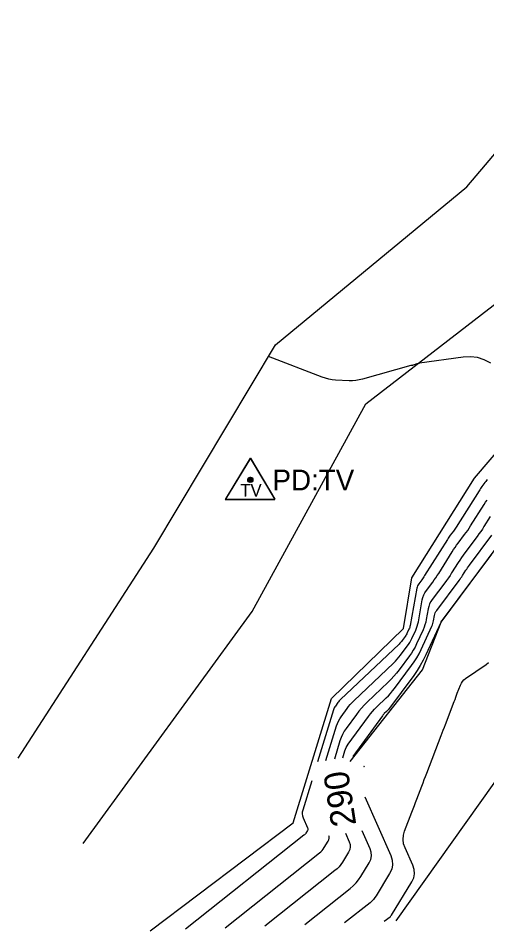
# Model space of a CAD drawing. Extents: x 1574966 to 1597594, y 720505 to 737840.
# Drawn here: x 1577468 to 1577580.8, y 724242.8 to 724462.3 of the extents above; entities that cross this region are included whole.
import ezdxf

# ---------------------------------------------------------------- set-up
doc = ezdxf.new("R2010")
doc.units = 0
for name, color, linetype in [('Default', 7, 'Continuous'), ('R_Contour Annot', 7, 'Continuous'), ('R_Contours', 7, 'Continuous'), ('S_BREAKLINE', 7, 'Continuous'), ('S_GRD_PT_SYM', 7, 'Continuous'), ('S_SECONDARY_CTL', 7, 'Continuous'), ('S_SECONDARY_CTL_ANNOT', 7, 'Continuous'), ('S_STREAM', 7, 'Continuous')]:
    doc.layers.add(name, color=color, linetype=linetype)

msp = doc.modelspace()

# ---------------------------------------------------------------- linework, layer by layer
at = {"layer": 'Default'}
for points in [[(1577523.86, 724351.22), (1577523.86, 724351.27), (1577523.86, 724351.22), (1577523.81, 724351.22), (1577523.86, 724351.22), (1577523.86, 724351.17), (1577523.86, 724351.22), (1577523.91, 724351.22)], [(1577523.86, 724351.22), (1577523.86, 724351.27), (1577523.86, 724351.22), (1577523.81, 724351.22), (1577523.86, 724351.22), (1577523.86, 724351.17), (1577523.86, 724351.22), (1577523.91, 724351.22)], [(1577523.86, 724351.22), (1577523.86, 724351.27), (1577523.86, 724351.22), (1577523.81, 724351.22), (1577523.86, 724351.22), (1577523.86, 724351.17), (1577523.86, 724351.22), (1577523.91, 724351.22)], [(1577523.91, 724351.26), (1577523.91, 724351.31), (1577523.91, 724351.26), (1577523.85, 724351.26), (1577523.91, 724351.26), (1577523.91, 724351.21), (1577523.91, 724351.26), (1577523.96, 724351.26)], [(1577523.91, 724351.26), (1577523.91, 724351.31), (1577523.91, 724351.26), (1577523.85, 724351.26), (1577523.91, 724351.26), (1577523.91, 724351.21), (1577523.91, 724351.26), (1577523.96, 724351.26)], [(1577523.91, 724351.26), (1577523.91, 724351.31), (1577523.91, 724351.26), (1577523.85, 724351.26), (1577523.91, 724351.26), (1577523.91, 724351.21), (1577523.91, 724351.26), (1577523.96, 724351.26)]]:
    msp.add_lwpolyline(points, dxfattribs=at)
at = {"layer": 'R_Contours'}
for points in [[(1577581.81, 724379.31), (1577580.23, 724380.12), (1577578.59, 724380.63), (1577576.89, 724380.83), (1577575.12, 724380.74), (1577564.65, 724379.28), (1577564.48, 724379.26), (1577564.31, 724379.22), (1577564.15, 724379.18), (1577563.98, 724379.12), (1577563.1, 724378.81), (1577563.05, 724378.8), (1577563, 724378.79), (1577562.96, 724378.78), (1577562.91, 724378.78), (1577562.71, 724378.76), (1577562.66, 724378.76), (1577562.61, 724378.75), (1577562.56, 724378.74), (1577562.51, 724378.73), (1577550.89, 724375.46), (1577550.09, 724375.27), (1577549.29, 724375.14), (1577548.48, 724375.08), (1577547.67, 724375.09), (1577544.39, 724375.25), (1577543.58, 724375.32), (1577542.78, 724375.46), (1577541.99, 724375.66), (1577541.22, 724375.92), (1577528.31, 724380.91)], [(1577580.94, 724351.3), (1577580.75, 724351.06), (1577580.56, 724350.82), (1577580.38, 724350.58), (1577579.64, 724349.61), (1577579.46, 724349.36), (1577579.28, 724349.12), (1577579.11, 724348.86), (1577578.95, 724348.61), (1577573.46, 724339.89), (1577573.3, 724339.64), (1577573.13, 724339.38), (1577572.95, 724339.14), (1577572.77, 724338.89), (1577572.04, 724337.92), (1577571.86, 724337.68), (1577571.69, 724337.43), (1577571.52, 724337.18), (1577571.35, 724336.92), (1577565.86, 724328.19), (1577565.69, 724327.94), (1577565.52, 724327.69), (1577565.35, 724327.44), (1577565.17, 724327.2), (1577564.44, 724326.23), (1577564.28, 724325.98), (1577564.14, 724325.72), (1577564.04, 724325.44), (1577563.97, 724325.15), (1577562.37, 724316.22), (1577562.32, 724315.98), (1577562.26, 724315.75), (1577562.18, 724315.52), (1577562.08, 724315.29), (1577561.68, 724314.41), (1577561.57, 724314.19), (1577561.45, 724313.98), (1577561.32, 724313.77), (1577561.18, 724313.57), (1577560.45, 724312.6), (1577560.28, 724312.37), (1577560.1, 724312.16), (1577559.9, 724311.95), (1577559.7, 724311.75), (1577545.64, 724298.42), (1577545.46, 724298.24), (1577545.29, 724298.05), (1577545.12, 724297.86), (1577544.97, 724297.65), (1577544.37, 724296.83), (1577544.23, 724296.62), (1577544.11, 724296.39), (1577544.01, 724296.17), (1577543.92, 724295.93), (1577540.08, 724283.41)], [(1577542.1, 724283.72), (1577544.66, 724292.06), (1577544.87, 724292.64), (1577545.12, 724293.2), (1577545.41, 724293.73), (1577545.75, 724294.24), (1577547.2, 724296.24), (1577547.57, 724296.73), (1577547.97, 724297.2), (1577548.38, 724297.66), (1577548.82, 724298.09), (1577558.39, 724307.17), (1577558.84, 724307.61), (1577559.27, 724308.07), (1577559.68, 724308.55), (1577560.07, 724309.05), (1577561.69, 724311.23), (1577562, 724311.67), (1577562.29, 724312.13), (1577562.55, 724312.6), (1577562.79, 724313.09), (1577563.7, 724315.06), (1577563.91, 724315.56), (1577564.09, 724316.07), (1577564.23, 724316.59), (1577564.35, 724317.12), (1577565.28, 724322.35), (1577565.43, 724322.96), (1577565.64, 724323.54), (1577565.92, 724324.09), (1577566.27, 724324.61), (1577567.8, 724326.64), (1577568.18, 724327.16), (1577568.54, 724327.68), (1577568.9, 724328.2), (1577569.24, 724328.74), (1577572.5, 724333.91), (1577572.84, 724334.45), (1577573.2, 724334.98), (1577573.57, 724335.5), (1577573.95, 724336.01), (1577575.49, 724338.05), (1577575.87, 724338.57), (1577576.23, 724339.09), (1577576.59, 724339.62), (1577576.94, 724340.16), (1577580.17, 724345.29), (1577580.52, 724345.83), (1577580.88, 724346.36)], [(1577581.67, 724342.42), (1577580.14, 724339.99), (1577579.75, 724339.39), (1577579.35, 724338.79), (1577578.94, 724338.21), (1577578.51, 724337.63), (1577575.55, 724333.7), (1577575.12, 724333.12), (1577574.71, 724332.53), (1577574.3, 724331.93), (1577573.91, 724331.32), (1577572.36, 724328.87), (1577571.97, 724328.26), (1577571.57, 724327.66), (1577571.15, 724327.06), (1577570.72, 724326.48), (1577567.71, 724322.48), (1577567.35, 724321.95), (1577567.07, 724321.39), (1577566.85, 724320.8), (1577566.7, 724320.18), (1577566.25, 724317.63), (1577566.12, 724317.01), (1577565.94, 724316.39), (1577565.73, 724315.78), (1577565.48, 724315.19), (1577563.91, 724311.77), (1577563.54, 724311.01), (1577563.13, 724310.28), (1577562.68, 724309.57), (1577562.2, 724308.88), (1577559.69, 724305.51), (1577559.08, 724304.73), (1577558.45, 724303.99), (1577557.78, 724303.27), (1577557.09, 724302.58), (1577552, 724297.76), (1577551.31, 724297.07), (1577550.65, 724296.35), (1577550.02, 724295.61), (1577549.43, 724294.83), (1577546.98, 724291.45), (1577546.51, 724290.75), (1577546.11, 724290.01), (1577545.76, 724289.25), (1577545.48, 724288.45), (1577544.13, 724284.03)], [(1577546.15, 724284.35), (1577546.68, 724286.06), (1577546.82, 724286.47), (1577547, 724286.87), (1577547.21, 724287.26), (1577547.46, 724287.62), (1577552.33, 724294.34), (1577552.8, 724294.95), (1577553.29, 724295.54), (1577553.81, 724296.11), (1577554.36, 724296.65), (1577556.59, 724298.77), (1577557.14, 724299.31), (1577557.66, 724299.87), (1577558.16, 724300.46), (1577558.63, 724301.06), (1577562.71, 724306.54), (1577563.36, 724307.47), (1577563.97, 724308.43), (1577564.52, 724309.42), (1577565.03, 724310.45), (1577567.61, 724316.07), (1577567.74, 724316.38), (1577567.85, 724316.69), (1577567.94, 724317.01), (1577568.01, 724317.33), (1577568.24, 724318.64), (1577568.32, 724318.96), (1577568.43, 724319.26), (1577568.57, 724319.55), (1577568.76, 724319.83), (1577574.18, 724327.03), (1577574.4, 724327.33), (1577574.61, 724327.63), (1577574.81, 724327.93), (1577575.01, 724328.24), (1577575.79, 724329.48), (1577575.99, 724329.79), (1577576.19, 724330.09), (1577576.41, 724330.39), (1577576.62, 724330.68), (1577582.06, 724337.91)], [(1577581.95, 724333.32), (1577577.69, 724327.67), (1577577.69, 724327.66), (1577577.68, 724327.65), (1577577.68, 724327.65), (1577577.67, 724327.64), (1577577.66, 724327.61), (1577577.65, 724327.6), (1577577.65, 724327.6), (1577577.64, 724327.59), (1577577.64, 724327.58), (1577569.81, 724317.17), (1577569.79, 724317.16), (1577569.79, 724317.14), (1577569.78, 724317.12), (1577569.78, 724317.11), (1577569.76, 724317.03), (1577569.76, 724317.01), (1577569.75, 724316.99), (1577569.75, 724316.98), (1577569.74, 724316.96), (1577566.14, 724309.13), (1577565.51, 724307.84), (1577564.81, 724306.58), (1577564.05, 724305.37), (1577563.22, 724304.19), (1577557.12, 724296.01), (1577557.01, 724295.87), (1577556.9, 724295.73), (1577556.78, 724295.61), (1577556.66, 724295.48), (1577556.15, 724295), (1577556.02, 724294.88), (1577555.91, 724294.75), (1577555.8, 724294.62), (1577555.69, 724294.48), (1577548.61, 724284.73)], [(1577556.15, 724245.05), (1577557.54, 724246.15), (1577557.63, 724246.23), (1577557.72, 724246.33), (1577557.8, 724246.42), (1577557.87, 724246.53), (1577562.76, 724254.54), (1577563.22, 724255.51), (1577563.41, 724256.5), (1577563.35, 724257.5), (1577563.02, 724258.52), (1577561.15, 724262.71), (1577560.81, 724263.71), (1577560.68, 724264.72), (1577560.75, 724265.73), (1577561.04, 724266.75), (1577562.79, 724271.31), (1577563.09, 724272.09), (1577563.39, 724272.87), (1577563.69, 724273.65), (1577563.99, 724274.43), (1577565.18, 724277.55), (1577565.48, 724278.34), (1577565.78, 724279.12), (1577566.08, 724279.9), (1577566.38, 724280.68), (1577569.85, 724289.71), (1577570.1, 724290.38), (1577570.36, 724291.05), (1577570.61, 724291.71), (1577570.86, 724292.38), (1577572.99, 724297.95), (1577573.17, 724298.44), (1577573.36, 724298.93), (1577573.55, 724299.41), (1577573.73, 724299.9), (1577574.48, 724301.85), (1577574.7, 724302.31), (1577574.98, 724302.73), (1577575.32, 724303.1), (1577575.72, 724303.42), (1577580.68, 724306.85), (1577581.22, 724307.28)], [(1577538.68, 724278.86), (1577536.52, 724271.82), (1577536.41, 724271.34), (1577536.4, 724270.87), (1577536.47, 724270.41), (1577536.63, 724269.95), (1577537.7, 724267.54), (1577537.76, 724267.37), (1577537.77, 724267.21), (1577537.74, 724267.05), (1577537.66, 724266.89), (1577537.28, 724266.27), (1577537.18, 724266.12), (1577537.07, 724265.98), (1577536.94, 724265.85), (1577536.81, 724265.73), (1577508.27, 724243.12)], [(1577551.43, 724274.95), (1577557.72, 724260.85), (1577558.08, 724259.74), (1577558.15, 724258.65), (1577557.94, 724257.57), (1577557.44, 724256.52), (1577554.2, 724251.21), (1577553.89, 724250.74), (1577553.53, 724250.31), (1577553.14, 724249.9), (1577552.72, 724249.53), (1577546.57, 724244.67)], [(1577546.8, 724266.23), (1577547.71, 724264.19), (1577547.92, 724263.56), (1577547.96, 724262.93), (1577547.84, 724262.31), (1577547.55, 724261.71), (1577546.09, 724259.3), (1577545.69, 724258.72), (1577545.26, 724258.18), (1577544.78, 724257.68), (1577544.25, 724257.23), (1577527.42, 724243.89)], [(1577537, 724244.28), (1577547.97, 724252.97), (1577548.69, 724253.6), (1577549.35, 724254.28), (1577549.95, 724255.02), (1577550.49, 724255.82), (1577552.5, 724259.11), (1577552.89, 724259.94), (1577553.06, 724260.79), (1577553, 724261.65), (1577552.72, 724262.52), (1577550.79, 724266.85)], [(1577517.85, 724243.51), (1577540.53, 724261.48), (1577540.86, 724261.77), (1577541.16, 724262.08), (1577541.44, 724262.42), (1577541.68, 724262.79), (1577542.61, 724264.3), (1577542.79, 724264.68), (1577542.86, 724265.07), (1577542.84, 724265.46), (1577542.79, 724265.61)]]:
    msp.add_lwpolyline(points, dxfattribs=at)
at = {"layer": 'S_BREAKLINE'}
for p, q in [((1577576, 724421.71), (1577610.41, 724462.27)), ((1577529.98, 724383.69), (1577576, 724421.71)), ((1577676.48, 724410.43), (1577558.94, 724245.17)), ((1577551.69, 724369.48), (1577597.66, 724405.03)), ((1577500.68, 724334.77), (1577529.98, 724383.69)), ((1577524.31, 724319.6), (1577551.69, 724369.48)), ((1577468.02, 724284.3), (1577500.68, 724334.77)), ((1577483.63, 724263.74), (1577524.31, 724319.6))]:
    msp.add_line(p, q, dxfattribs=at)
at = {"layer": 'S_GRD_PT_SYM'}
msp.add_lwpolyline([(1577551.27, 724282.27), (1577551.27, 724282.32), (1577551.27, 724282.27), (1577551.22, 724282.27), (1577551.27, 724282.27), (1577551.27, 724282.22), (1577551.27, 724282.27), (1577551.32, 724282.27)], dxfattribs=at)
msp.add_lwpolyline([(1577551.27, 724282.27), (1577551.27, 724282.32), (1577551.27, 724282.27), (1577551.22, 724282.27), (1577551.27, 724282.27), (1577551.27, 724282.22), (1577551.27, 724282.27), (1577551.32, 724282.27)], dxfattribs=at)
msp.add_lwpolyline([(1577551.27, 724282.27), (1577551.27, 724282.32), (1577551.27, 724282.27), (1577551.22, 724282.27), (1577551.27, 724282.27), (1577551.27, 724282.22), (1577551.27, 724282.27), (1577551.32, 724282.27)], dxfattribs=at)
at = {"layer": 'S_SECONDARY_CTL'}
for p, q in [((1577523.89, 724356.45), (1577517.87, 724346.54)), ((1577523.89, 724356.45), (1577517.87, 724346.54)), ((1577523.89, 724356.45), (1577517.87, 724346.54)), ((1577523.91, 724356.48), (1577517.89, 724346.57)), ((1577523.91, 724356.48), (1577517.89, 724346.57)), ((1577523.91, 724356.48), (1577517.89, 724346.57)), ((1577523.89, 724356.45), (1577529.78, 724346.54)), ((1577523.89, 724356.45), (1577529.78, 724346.54)), ((1577523.89, 724356.45), (1577529.78, 724346.54)), ((1577523.91, 724356.48), (1577529.8, 724346.57)), ((1577523.91, 724356.48), (1577529.8, 724346.57)), ((1577523.91, 724356.48), (1577529.8, 724346.57)), ((1577517.87, 724346.54), (1577529.78, 724346.54)), ((1577517.87, 724346.54), (1577529.78, 724346.54)), ((1577517.87, 724346.54), (1577529.78, 724346.54)), ((1577517.89, 724346.57), (1577529.8, 724346.57)), ((1577517.89, 724346.57), (1577529.8, 724346.57)), ((1577517.89, 724346.57), (1577529.8, 724346.57))]:
    msp.add_line(p, q, dxfattribs=at)
for centre, radius in [((1577523.89, 724351.23), 0.622), ((1577523.89, 724351.23), 0.622), ((1577523.89, 724351.23), 0.622), ((1577523.91, 724351.26), 0.622), ((1577523.91, 724351.26), 0.622), ((1577523.91, 724351.26), 0.622), ((1577523.89, 724351.23), 0.365), ((1577523.89, 724351.23), 0.365), ((1577523.89, 724351.23), 0.365), ((1577523.91, 724351.26), 0.365), ((1577523.91, 724351.26), 0.365), ((1577523.91, 724351.26), 0.365), ((1577523.89, 724351.23), 0.207), ((1577523.89, 724351.23), 0.207), ((1577523.89, 724351.23), 0.207), ((1577523.91, 724351.26), 0.207), ((1577523.91, 724351.26), 0.207), ((1577523.91, 724351.26), 0.207)]:
    msp.add_circle(centre, radius, dxfattribs=at)
at = {"layer": 'S_STREAM'}
for p, q in [((1577577.85, 724351.6), (1577601.06, 724378.94)), ((1577569.87, 724317.01), (1577601.27, 724359.34)), ((1577562.79, 724327.7), (1577577.85, 724351.6)), ((1577560.77, 724315.48), (1577562.79, 724327.7)), ((1577565.38, 724305.56), (1577569.87, 724317.01)), ((1577543.4, 724298.65), (1577560.77, 724315.48)), ((1577547.97, 724283.48), (1577565.38, 724305.56)), ((1577534.21, 724268.7), (1577543.4, 724298.65)), ((1577499.81, 724242.78), (1577534.21, 724268.7))]:
    msp.add_line(p, q, dxfattribs=at)

# ---------------------------------------------------------------- texts
at = {"layer": 'R_Contour Annot'}
msp.add_text('290', height=6, rotation=98.7883, dxfattribs=at).set_placement((1577549.42, 724268.31))
at = {"layer": 'S_SECONDARY_CTL'}
for p in [(1577521.48, 724347.21), (1577521.48, 724347.21), (1577521.48, 724347.21), (1577521.5, 724347.23), (1577521.5, 724347.23), (1577521.5, 724347.23)]:
    msp.add_text('TV', height=3, rotation=360, dxfattribs=at).set_placement(p)
at = {"layer": 'S_SECONDARY_CTL_ANNOT'}
msp.add_text('PD:TV', height=5, dxfattribs=at).set_placement((1577529.23, 724348.7))

doc.saveas('drawing.dxf')
